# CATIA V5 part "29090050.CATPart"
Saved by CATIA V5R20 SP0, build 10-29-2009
Part number: 29090050
Definition: NONE
Nomenclature: 29090050
Source: Unknown
Description: 29090050
Bounding box of the stored display mesh (mm): x -25 to 44.548, y -59 to 93.548, z -49 to 49
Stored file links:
  C:\Users\Utente\Desktop\IO LAVORO\3D X SITO CF\X SITO\PLASTICA\RF1\29090050.CATPart
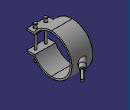
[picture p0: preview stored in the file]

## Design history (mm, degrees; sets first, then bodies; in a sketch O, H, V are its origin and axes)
Body1 "29090050" (main body)
  Solid1: solid without history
